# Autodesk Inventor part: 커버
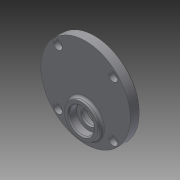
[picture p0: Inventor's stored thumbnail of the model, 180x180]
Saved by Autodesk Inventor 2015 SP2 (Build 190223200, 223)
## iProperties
Created: 2015-06
Part Number: 커버
Material: 일반
Document SubType Name: Modeling
Designer: AMC
Density: 1 g/cm^3
Appearance: 기본값
Author: AMC
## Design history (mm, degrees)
sketch "스케치1"
  geometry: C1 r 40 at (0, 0); 1 further point
  constraints: 1 centre point, 1 coincident
  dimensions: "d0" = 80 diameter of C1
extrude "돌출1" new body sketch "스케치1" distance "d1" = 9; taper "d2" = 0 deg
sketch "스케치2"
  geometry: C1 r 15 at (0, -20); 1 further point
  constraints: 1 centre point, 1 vertical alignment
  dimensions: "d3" = 30 diameter of C1; "d4" = 20 distance of C1.centre point (0, 0)
extrude "돌출2" join sketch "스케치2" distance "d5" = 4; taper "d6" = 0 deg
sketch "스케치3"
  geometry: C1 r 14 at (0, -20); C2 r 14 at (0, 11); 1 further point
  constraints: 2 centre point, 2 vertical alignment
  dimensions: "d7" = 28 diameter of C1; "d8" = 20 distance of point (0, 0) C1.centre; "d9" = 28 diameter of C2; "d10" = 11 distance of point (0, 0) C2.centre
extrude "돌출3" join sketch "스케치3" distance "d11" = 3; taper "d12" = 0 deg
hole "구멍1" diameter "d15" = 18; stored, may be unused: countersink angle "d19" = 90 deg, drill point angle "d21" = 0 deg; dims "d13" = 10, "d14" = 10, "d16" = 6, "d17" = 22, "d18" = 7, "d20" = 8
hole "구멍2" diameter "d24" = 15; stored, may be unused: countersink angle "d28" = 90 deg, drill point angle "d30" = 0 deg; dims "d22" = 10, "d23" = 10, "d25" = 6, "d26" = 22, "d27" = 7, "d29" = 8
sketch "스케치4"
  geometry: C1 r 15 at (0, 0) reference; C2 r 11 at (0, 0); 1 further point
  constraints: 1 centre point, 1 coincident
  dimensions: "d31" = 22 diameter of C2
extrude "돌출4" cut sketch "스케치4" distance "d32" = 7; taper "d33" = 0 deg
sketch "스케치5" dims "d34" = 70
  geometry: L1 (0, 0)-(0, 53.652); L2 (0, 0)-(-41.251, 41.251); 2 further points
  constraints: 4 end point, 1 coincident, 1 point on line, 1 vertical, 3 other
  dimensions: "d35" = 45 deg angle of L2 L1
hole "구멍3" sketch "스케치5" at (-24.749, 24.749) diameter "d36" = 4.5; stored, may be unused: countersink angle "d40" = 90 deg, drill point angle "d42" = 0 deg; dims "d37" = 6, "d38" = 8, "d39" = 4.4, "d41" = 8
fillet "모깎기1" dims "d46" = 0.3
chamfer "모따기1" distance "d47" = 1; stored, may be unused: second distance "d48" = 2, angle "d49" = 45 deg
fillet "모깎기2" dims "d50" = 2
fillet "모깎기3" dims "d51" = 2
chamfer "모따기2" distance "d52" = 1; stored, may be unused: second distance "d53" = 2, angle "d54" = 45 deg
node "솔리드1"
pattern_circular "원형 패턴1" dims angle "d44" = 360 deg
